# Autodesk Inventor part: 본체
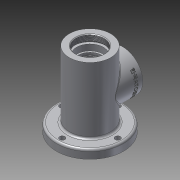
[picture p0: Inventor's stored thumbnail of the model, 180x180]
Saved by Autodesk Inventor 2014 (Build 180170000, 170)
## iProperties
Created: 2016-08
Part Number: 본체
Material: 알루미늄 6061
Document SubType Name: Modeling
Designer: USER
Density: 2.71138 g/cm^3
Appearance: 알루미늄 - 평지
Mass: 767 g
Surface Area: 622.621 cm^2
Volume: 282.882 cm^3
Author: USER
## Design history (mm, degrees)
sketch "스케치3"
  geometry: C1 r 31 at (0, 0); 1 further point
  constraints: 1 centre point, 1 coincident
  dimensions: "d14" = 62 diameter of C1
extrude "돌출1" new body sketch "스케치3" distance "d15" = 115; taper "d16" = 0 deg
node "작업 평면1"
sketch "스케치5"
  geometry: C1 r 50 at (0, 0); 1 further point
  constraints: 1 centre point, 1 coincident
  dimensions: "d19" = 100 diameter of C1
extrude "돌출2" join sketch "스케치5" distance "d20" = 13; taper "d21" = 0 deg
sketch "스케치8"
  geometry: L1 (0, 0)-(0, 115); L2 (0, 0)-(21, 0); L3 (21, 0)-(16, 14); L4 (16, 14)-(12.904, 14); L5 (12.904, 14)-(12.5, 14.7); L6 (12.5, 14.7)-(12.5, 22); L7 (12.5, 22)-(10, 22); L8 (10, 22)-(10, 24.7); L9 (10, 24.7)-(16.5, 24.7); L10 (16.5, 24.7)-(16.5, 29.7); L11 (16.5, 29.7)-(17.5, 29.7); L12 (17.5, 29.7)-(17.5, 38.946); L13 (26, 40)-(26, 78); L14 (26, 78)-(18.262, 78); L15 (17.5, 79.32)-(17.5, 89); L16 (17.5, 89)-(18.5, 89); L17 (18.5, 89)-(18.5, 90.75); L18 (18.5, 90.75)-(17.5, 90.75); L19 (17.5, 90.75)-(17.5, 94); L20 (17.5, 94)-(20, 94); L21 (20, 94)-(20, 103); L22 (20, 103)-(24, 103); L23 (24, 103)-(24, 106); L24 (24, 106)-(21, 106); L25 (21, 106)-(21, 115); L26 (31, 115)-(-31, 115) reference; L27 (26, 59)-(44.925, 59); L28 (21, 115)-(0, 115); L29 (26, 40)-(18.108, 40); L30 (18.108, 40)-(17.5, 38.946); L31 (18.262, 78)-(17.5, 79.32)
  constraints: 60 end point, 14 parallel, 9 perpendicular, 2 midpoint, 1 collinear, 1 point on line, 1 vertical
  dimensions: "d29" = 42 diameter of L2.end L1; "d30" = 32 diameter of L3.end L1; "d31" = 14 vertical distance of L2.end L3.end; "d32" = 25 diameter of L6 L1; "d33" = 7.3 distance of L5.end L6.end; "d34" = 30 deg angle of L6 L5; "d35" = 0.7 vertical distance of L4.end L5.end; "d36" = 20 diameter of L8 L1; "d37" = 2.7 distance of L7.end L8.end; "d38" = 33 diameter of L10 L1; "d40" = 35 diameter of L12 L1; "d42" = 35 diameter of L15 L1; "d43" = 37 diameter of L17 L1; "d44" = 35 diameter of L19 L1; "d45" = 40 diameter of L21 L1; "d46" = 48 diameter of L23 L1; "d47" = 42 diameter of L25 L1; "d48" = 12 vertical distance of L22.end L25.end; "d49" = 3 distance of L22.end L23.end; "d50" = 21 vertical distance of L20.end L25.end; "d51" = 26 vertical distance of L16.end L25.end; "d52" = 1.75 distance of L16.end L17.end; "d56" = 5 distance of L9.end L10.end; "d57" = 56 distance from line of L27.end L26; "d59" = 52 diameter of L13 L1; "d75" = 30 deg angle of L12 L30; "d77" = 38 distance between parallel lines of L29 L14; "d78" = 30 deg angle of L31 L15; "d79" = 1.05391 vertical distance of L29.end L12.end; "d80" = 1.31965 vertical distance of L14.end L15.start
revolve "회전1" sketch "스케치8" stored, may be unused: angle "d60" = 90 deg
feature "스레드1" dims "d61" = 9, "d62" = 0
node "작업 평면5"
sketch "스케치10"
  geometry: L1 (31, 115)-(-31, 115) reference; C1 r 30 at (0, 59); 1 further point
  constraints: 1 centre point, 1 vertical alignment
  dimensions: "d66" = 60 diameter of C1; "d67" = 56 distance from line of C1.centre L1
extrude "돌출3" join sketch "스케치10" stored distance "d68" = 13; taper "d69" = 0 deg
sketch "스케치12"
  geometry: C1 r 30 at (0, 0) reference; C2 r 19 at (0, 0); 1 further point
  constraints: 1 centre point, 1 coincident
  dimensions: "d70" = 38 diameter of C2
extrude "돌출4" cut sketch "스케치12" stored distance "d71" = 13; taper "d72" = 0 deg
fillet "모깎기1" dims "d73" = 3, "d74" = 0.3
sketch "스케치17" dims "d81" = 48
  geometry: C1 r 30 at (0, 0) reference; 3 further points
  constraints: 2 horizontal alignment, 1 coincident, 2 other
hole "구멍2" sketch "스케치17" at (-24, 0) diameter "d82" = 3.242; stored, may be unused: countersink angle "d86" = 90 deg, drill point angle "d88" = 118 deg; dims "d83" = 8, "d84" = 4, "d85" = 2, "d87" = 10
sketch "스케치18" dims "d92" = 83
  geometry: C1 r 31 at (0, 0) reference; C2 r 4 at (41.5, 0); 1 further point
  constraints: 2 horizontal alignment, 1 centre point, 1 coincident, 2 other
  dimensions: "d93" = 8 diameter of C2
extrude "돌출5" cut sketch "스케치18" distance "d94" = 13; taper "d95" = 0 deg
fillet "모깎기2" dims "d99" = 3
node "작업 평면6"
sketch "스케치19"
  geometry: L1 (-18, 56)-(-80, 56) reference; L2 (0, 30)-(0, -30) reference; 2 further points
  constraints: 1 other
  dimensions: "d100" = 56 distance from line of point (-10, 0) L1; "d101" = 10 distance from line of L2 point (-10, 0)
feature "엠보싱1" sketch "스케치19" dims "d102" = 0.5, "d103" = 0
node "작업 평면7"
sketch "스케치20"
  geometry: 1 further point
chamfer "모따기1" distance "d104" = 1; stored, may be unused: second distance "d105" = 2, angle "d106" = 45 deg
node "솔리드1"
pattern_circular "원형 패턴1" dims angle "d90" = 360 deg
pattern_circular "원형 패턴2" dims angle "d97" = 360 deg
other parameters: "d18" = 3, "d65" = 49
